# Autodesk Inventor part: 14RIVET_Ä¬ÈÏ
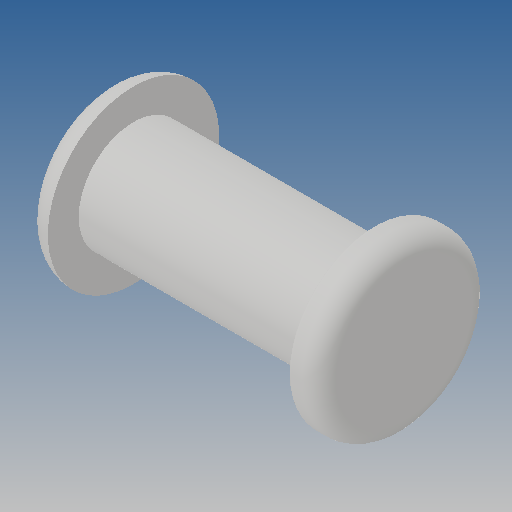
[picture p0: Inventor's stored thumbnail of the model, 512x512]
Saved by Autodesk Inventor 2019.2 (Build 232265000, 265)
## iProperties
Created: 2010-06
Part Number: 14RIVET_Ä¬ÈÏ
Material: Ogólny
Document SubType Name: Modeling
Designer: CADENGINEERING4
Density: 1 g/cm^3
Appearance: Domyślna
Author: CADENGINEERING4
Revision Number: ÈÎºÎ
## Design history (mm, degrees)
feature "NONE"
node "Bryła1"
